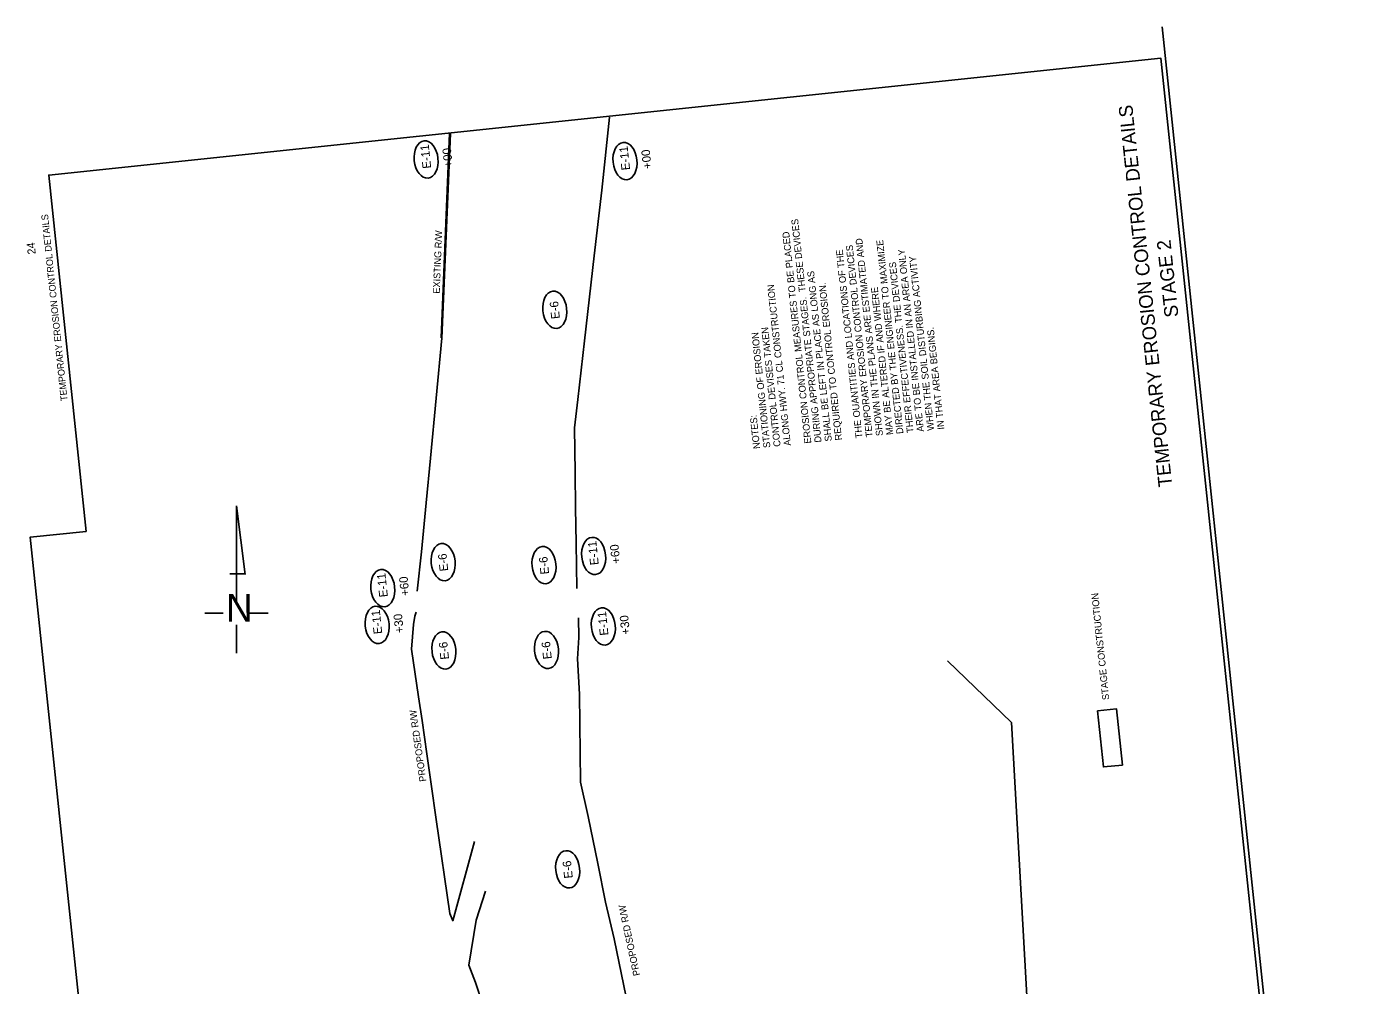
# Model space of a CAD drawing. Extents: x 633554 to 635141, y 286699 to 290011.
# Drawn here: x 633839 to 635006, y 289173 to 290011 of the extents above; entities that cross this region are included whole.
import ezdxf

# ---------------------------------------------------------------- set-up
doc = ezdxf.new("R2010")
doc.units = 0
for name, color, linetype in [('24', 7, 'Continuous'), ('R_Axis Annot', 7, 'Continuous'), ('S_BASELINE', 7, 'Continuous'), ('S_BRIDGE', 7, 'Continuous'), ('S_GAS_UTILITIES', 7, 'Continuous'), ('S_PRIMARY_CTL', 7, 'Continuous')]:
    doc.layers.add(name, color=color, linetype=linetype)

msp = doc.modelspace()

# ---------------------------------------------------------------- linework, layer by layer
at = {"layer": '24'}
msp.add_lwpolyline([(634797.3, 289365.8), (634792.2, 289414.8), (634775.6, 289413.1), (634780.8, 289364.1)], close=True, dxfattribs=at)
at = {"layer": 'R_Axis Annot'}
msp.add_line((634202.3, 289739.2), (634209.7, 289918), dxfattribs=at)
for points in [[(634348.8, 289932.2), (634342.1, 289868.4), (634335.4, 289811), (634327.1, 289736.6), (634321.1, 289685.5), (634318.4, 289660.7), (634318.8, 289621.7), (634319.2, 289590.7), (634319.8, 289559.9), (634320.4, 289520.2)], [(634180.7, 289517.7), (634184.4, 289552.1), (634188.7, 289595.2), (634192.4, 289634.2), (634202.3, 289739.2)], [(634230.8, 289299), (634211.8, 289229.7), (634209.3, 289235.9), (634197.2, 289318.3), (634193, 289349), (634189.2, 289375.6), (634185.1, 289404.8), (634181.9, 289425.4), (634175.7, 289467), (634177.6, 289488.6), (634178.8, 289496), (634179.7, 289499.5)], [(634321.8, 289494.6), (634322, 289477.3), (634321, 289458.8), (634322.5, 289427.9), (634323.4, 289350.9), (634330.1, 289320.9), (634338.7, 289279.7), (634345.5, 289245.9), (634353, 289213.9), (634363.5, 289162.9), (634373, 289118.2), (634379.2, 289087.9), (634386.4, 289055.4), (634438.1, 288904)], [(634335.4, 288869.2), (634273.5, 289052), (634264.8, 289077.5), (634245.6, 289132.5), (634237.7, 289157.1), (634231.8, 289175.6), (634226, 289190.7), (634232.4, 289230.1), (634240.4, 289255.4)]]:
    msp.add_lwpolyline(points, dxfattribs=at)
for centre in [(634188.5, 289895.3), (634362.4, 289893.9), (634301, 289763.9), (634203.4, 289543.2), (634291.6, 289540.6), (634335, 289548.6), (634150.6, 289520.5), (634145.7, 289488.3), (634343.5, 289487), (634204.1, 289466), (634293.8, 289466.4), (634312.3, 289274.6)]:
    msp.add_ellipse(centre, major_axis=(-1.7, 16.3), ratio=0.638788, dxfattribs=at)
at = {"layer": 'S_BASELINE'}
msp.add_lwpolyline([(634998.3, 288392), (633976.9, 288284.7), (633842.3, 289565), (633891.2, 289570.1), (633858.5, 289881.6), (634831, 289983.8)], close=True, dxfattribs=at)
at = {"layer": 'S_BRIDGE'}
for p, q in [((635006.2, 288353.3), (634832, 290011.4)), ((634700.4, 289403.1), (634644.3, 289456.9))]:
    msp.add_line(p, q, dxfattribs=at)
msp.add_lwpolyline([(634872.2, 287708.2), (634772.2, 288125), (634700.4, 289403.1)], dxfattribs=at)
at = {"layer": 'S_PRIMARY_CTL'}
for p, q in [((634022.7, 289592.5), (634030.2, 289532.5)), ((634022.7, 289508.6), (634022.7, 289592.5)), ((634016.8, 289533), (634030.2, 289533)), ((633995.1, 289498.7), (634011, 289498.7)), ((634033.3, 289498.7), (634050.3, 289498.7)), ((634022.7, 289463.6), (634022.7, 289488.3))]:
    msp.add_line(p, q, dxfattribs=at)
msp.add_lwpolyline([(634201.7, 289739.4), (634208.9, 289918.4)], dxfattribs=at)

# ---------------------------------------------------------------- texts
at = {"layer": 'R_Axis Annot'}
for s, height, rotation, p in [('E-11', 7.5, 96.0379, (634193, 289887.7)), ('+00', 7.5, 96.0379, (634211.9, 289888.8)), ('E-11', 7.5, 96.0379, (634366.9, 289886.3)), ('+00', 7.5, 96.0379, (634385.8, 289887.4)), ('EXISTING R/W', 6, 87.6932, (634200.4, 289777.9)), ('E-6', 7.5, 96.0379, (634305.5, 289756.2)), ('E-11', 7.5, 96.0379, (634339.5, 289541)), ('+60', 7.5, 96.0379, (634358.4, 289542.2)), ('E-6', 7.5, 96.0379, (634207.9, 289535.6)), ('E-6', 7.5, 96.0379, (634296.1, 289532.9)), ('E-11', 7.5, 96.0379, (634155.1, 289512.9)), ('+60', 7.5, 96.0379, (634174, 289514.1)), ('E-11', 7.5, 96.0379, (634150.2, 289480.7)), ('+30', 7.5, 96.0379, (634169.1, 289481.5)), ('E-11', 7.5, 96.0379, (634348, 289479.4)), ('+30', 7.5, 96.0379, (634366.9, 289480.2)), ('E-6', 7.5, 96.0379, (634208.6, 289458.4)), ('E-6', 7.5, 96.0379, (634298.4, 289458.7)), ('PROPOSED R/W', 6, 98.1444, (634188.8, 289351.7)), ('E-6', 7.5, 96.0379, (634316.8, 289267)), ('PROPOSED R/W', 6, 101.9585, (634375.7, 289182.1))]:
    msp.add_text(s, height=height, rotation=rotation, dxfattribs=at).set_placement(p)
at = {"layer": 'S_BRIDGE'}
msp.add_text('24', height=7, rotation=96, dxfattribs=at).set_placement((633847.2, 289812.7))
at = {"layer": 'S_GAS_UTILITIES'}
for s, height, p in [('TEMPORARY EROSION CONTROL DETAILS', 12.052, (634841, 289609.6)), ('TEMPORARY EROSION CONTROL DETAILS', 5.888, (633875, 289684.5)), ('STAGE 2', 12.05, (634846.4, 289757.9))]:
    msp.add_text(s, height=height, rotation=96, dxfattribs=at).set_placement(p)
at = {"layer": 'S_PRIMARY_CTL'}
for s, height, rotation, p in [('DURING APPROPRIATE STAGES.  THESE DEVICES', 6, 96, (634534.3, 289648.1)), ('EROSION CONTROL MEASURES TO BE PLACED', 6, 96, (634525.4, 289647.2)), ('SHOWN IN THE PLANS ARE ESTIMATED AND ', 6, 96, (634588, 289653.8)), ('DIRECTED BY THE ENGINEER TO MAXIMIZE ', 6, 96, (634605.9, 289655.6)), ('THE OUANTITIES AND LOCATIONS OF THE ', 6, 96, (634570.1, 289651.9)), ('TEMPORARY EROSION CONTROL DEVICES', 6, 96, (634579.1, 289652.8)), ('ARE TO BE INSTALLED IN AN AREA ONLY ', 6, 96, (634623.8, 289657.5)), ('THEIR EFFECTIVENESS. THE DEVICES', 6, 96, (634614.9, 289656.6)), ('WHEN THE SOIL DISTURBING ACTIVITY', 6, 96, (634632.8, 289658.5)), ('SHALL BE LEFT IN PLACE AS LONG AS', 6, 96, (634543.3, 289649.1)), ('ALONG HWY. 71 CL CONSTRUCTION', 6, 96, (634507.5, 289645.3)), ('REQUIRED TO CONTROL EROSION.', 6, 96, (634552.2, 289650)), ('MAY BE ALTERED IF AND WHERE', 6, 96, (634597, 289654.7)), ('STATIONING OF EROSION', 6, 96, (634489.6, 289643.4)), ('CONTROL DEVISES TAKEN', 6, 96, (634498.5, 289644.4)), ('IN THAT AREA BEGINS.', 6, 96, (634641.7, 289659.4)), ('NOTES:', 6, 96, (634480.6, 289642.5)), ('N', 24, 360, (634013.6, 289491.3)), ('STAGE CONSTRUCTION', 6, 96, (634785.9, 289423))]:
    msp.add_text(s, height=height, rotation=rotation, dxfattribs=at).set_placement(p)

doc.saveas('drawing.dxf')
